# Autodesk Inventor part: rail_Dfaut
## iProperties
Created: 2007-07
Part Number: rail_Dfaut
Document SubType Name: Modeling
Designer: EF
Density: 1 g/cm^3
Mass: 624.404 g
Surface Area: 3105.3 cm^2
Volume: 624.404 cm^3
Author: EF
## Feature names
1. Extrusion1
